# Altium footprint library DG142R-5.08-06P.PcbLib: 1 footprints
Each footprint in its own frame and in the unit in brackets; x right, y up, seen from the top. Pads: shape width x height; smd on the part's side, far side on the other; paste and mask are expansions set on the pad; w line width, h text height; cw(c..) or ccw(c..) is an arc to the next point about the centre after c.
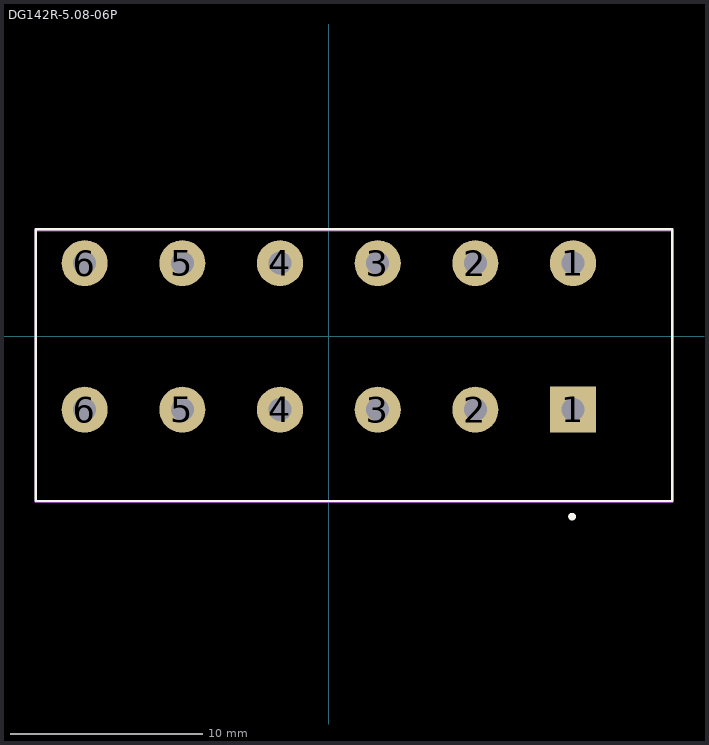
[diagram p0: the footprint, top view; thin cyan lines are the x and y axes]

## DG142R-5.08-06P [mm]
pads (12):
  rect 2.4x2.4 hole 1.2: 1(12.7,-3.81)
  round 2.4 hole 1.2: 1(12.7,3.81) 2(7.62,-3.81) 2(7.62,3.81) 3(2.54,-3.81) 3(2.54,3.81) 4(-2.54,-3.81) 4(-2.54,3.81) 5(-7.62,-3.81) 5(-7.62,3.81) 6(-12.7,-3.81) 6(-12.7,3.81)
Top Overlay:
  circle w0.2: c12.649,-9.373 r0.1
  lines w0.127: -15.24,-8.56 -15.24,5.563 17.856,5.563 17.856,-8.56 -15.24,-8.56
Mechanical 13:
  lines w0.127: -15.24,-8.611 17.856,-8.611 17.856,5.512 -15.24,5.512 -15.24,-8.611
3D body "DG142R-5.08-06P.stp": height 13.47, standoff -3.43, extent -15.227,-8.54 17.793,5.563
